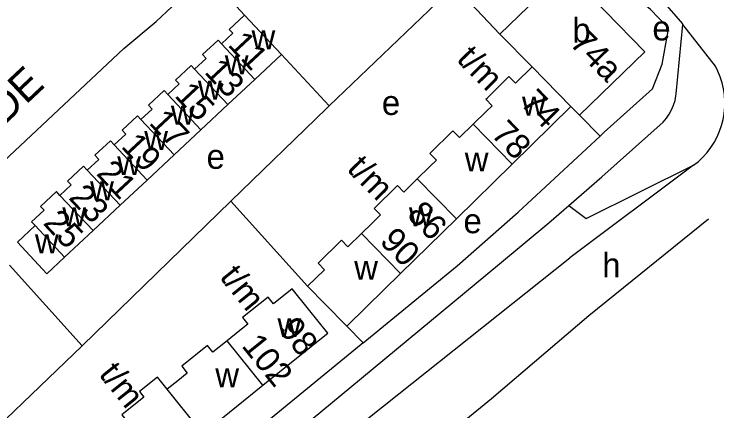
# Model space of a CAD drawing. Extents: x 161141 to 163125, y 381621 to 383200.
# Drawn here: x 162382.8 to 162497.1, y 381773.2 to 381837.8 of the extents above; entities that cross this region are included whole.
import ezdxf

# ---------------------------------------------------------------- set-up
doc = ezdxf.new("R2010")
doc.units = 0
for name, color, linetype in [('BLT_Basislijn', 7, 'Continuous'), ('BLT_Bebouwing', 7, 'Continuous'), ('BLT_Centroide', 7, 'Continuous'), ('BLT_Huisnummer', 7, 'Continuous'), ('BLT_Huisnummer_ tussenligend', 7, 'Continuous'), ('BLT_Huisnummer_reeks', 7, 'Continuous'), ('BLT_Onderverdeling_panden', 7, 'Continuous'), ('BLT_Straatnaam', 7, 'Continuous'), ('BLT_Vlakafsluiter', 7, 'Continuous')]:
    doc.layers.add(name, color=color, linetype=linetype)

msp = doc.modelspace()

# ---------------------------------------------------------------- linework, layer by layer
at = {"layer": 'BLT_Basislijn'}
for p, q in [((162414.1, 381844.29), (162420.31, 381837.61)), ((162461.81, 381834.53), (162454.36, 381842.38)), ((162490.46, 381824.8), (162491.54, 381836.11)), ((162491.54, 381836.11), (162491.45, 381836.22)), ((162496.85, 381829.3), (162491.54, 381836.11)), ((162434.07, 381822.85), (162426.31, 381831.19)), ((162478.08, 381817.94), (162474.76, 381821.34)), ((162464.78, 381805.57), (162478.08, 381817.94)), ((162393.89, 381783.83), (162418.1, 381807.37)), ((162430.56, 381793.5), (162418.1, 381807.37)), ((162476.27, 381788.75), (162495.69, 381804.49)), ((162382.12, 381796.96), (162393.89, 381783.83)), ((162439.57, 381784.3), (162436.92, 381787.02)), ((162367.84, 381758.79), (162393.89, 381783.83)), ((162416.56, 381759.84), (162439.32, 381778.56))]:
    msp.add_line(p, q, dxfattribs=at)
for points in [[(162451.86, 381872.61), (162467.34, 381859.82), (162479.4, 381849.56), (162484.61, 381844.16), (162491.45, 381836.22)], [(162488.94, 381835.49), (162488.88, 381835.83), (162486.28, 381838.55), (162476.14, 381846.96), (162472.45, 381850.34), (162467.02, 381854.86)], [(162373.17, 381806.36), (162400.66, 381832.19), (162405.95, 381836.6), (162413.57, 381843.79), (162414.1, 381844.29)], [(162434.07, 381822.85), (162453.97, 381842), (162454.36, 381842.38)], [(162488.15, 381829.64), (162489.07, 381834.73), (162488.94, 381835.49)], [(162478.08, 381817.94), (162478.77, 381818.58), (162486.59, 381825.6), (162488.15, 381829.64)], [(162498.1, 381820.61), (162498.25, 381821.63), (162498.34, 381822.63), (162498.36, 381823.64), (162498.29, 381824.64), (162498.14, 381825.64), (162497.92, 381826.61), (162497.62, 381827.57), (162497.24, 381828.51), (162496.85, 381829.3)], [(162488.35, 381820.21), (162488.87, 381820.83), (162489.32, 381821.49), (162489.71, 381822.2), (162490.02, 381822.94), (162490.26, 381823.72), (162490.42, 381824.51), (162490.46, 381824.8)], [(162434.07, 381822.85), (162433.64, 381822.43), (162418.1, 381807.37)], [(162472.99, 381806.65), (162478.36, 381811.3), (162488.35, 381820.21)], [(162493.29, 381813.19), (162494.07, 381813.82), (162494.8, 381814.52), (162495.47, 381815.27), (162496.08, 381816.07), (162496.62, 381816.91), (162497.1, 381817.8), (162497.5, 381818.72), (162497.83, 381819.67), (162498.1, 381820.61)], [(162472.99, 381806.65), (162475.84, 381804.55), (162493.29, 381813.19)], [(162439.32, 381778.56), (162461.72, 381797.17), (162469.73, 381803.83), (162472.99, 381806.65)], [(162439.57, 381784.3), (162454.87, 381796.81), (162464.78, 381805.57)], [(162428.68, 381762.74), (162473.16, 381798.14)], [(162443.23, 381761.14), (162460.45, 381775.25), (162476.27, 381788.75)], [(162439.57, 381784.3), (162439.24, 381784.03), (162407.7, 381758.1), (162404.51, 381755.23), (162398.2, 381750)]]:
    msp.add_lwpolyline(points, dxfattribs=at)
at = {"layer": 'BLT_Bebouwing'}
for p, q in [((162461.81, 381834.53), (162472.45, 381844.9)), ((162467.02, 381829.21), (162461.81, 381834.53)), ((162426.31, 381831.19), (162421.99, 381827.15)), ((162421.99, 381827.15), (162417.6, 381823.05)), ((162417.6, 381823.05), (162413.22, 381818.95)), ((162463.82, 381813.38), (162473.35, 381822.75)), ((162474.76, 381821.34), (162473.35, 381822.75)), ((162413.22, 381818.95), (162408.86, 381814.88)), ((162408.86, 381814.88), (162404.49, 381810.79)), ((162454.74, 381804.49), (162463.82, 381813.38)), ((162404.49, 381810.79), (162400.09, 381806.68)), ((162400.09, 381806.68), (162395.68, 381802.56)), ((162445.67, 381795.6), (162454.74, 381804.49)), ((162413.51, 381769.56), (162423.3, 381777.43))]:
    msp.add_line(p, q, dxfattribs=at)
for points in [[(162472.45, 381844.9), (162485.33, 381831.63), (162474.76, 381821.34)], [(162420.31, 381837.61), (162417.83, 381835.3), (162418.42, 381834.67), (162416.58, 381832.94)], [(162426.31, 381831.19), (162423.72, 381833.96), (162420.31, 381837.61)], [(162416.58, 381832.94), (162416, 381833.56), (162413.46, 381831.19), (162414.04, 381830.57), (162412.19, 381828.84)], [(162412.19, 381828.84), (162411.63, 381829.43), (162409.08, 381827.05), (162409.67, 381826.42), (162407.83, 381824.71)], [(162457.45, 381819.87), (162459.65, 381822.01), (162460.53, 381822.86), (162459.49, 381823.92), (162459.71, 381824.13), (162463.27, 381827.63), (162464.32, 381826.57), (162467.02, 381829.21)], [(162407.83, 381824.71), (162407.24, 381825.34), (162404.7, 381822.97), (162405.29, 381822.34), (162403.47, 381820.65)], [(162403.47, 381820.65), (162402.91, 381821.25), (162400.4, 381818.9), (162400.99, 381818.26), (162399.13, 381816.53)], [(162448.37, 381810.99), (162450.42, 381812.99), (162451.48, 381814.03), (162450.43, 381815.1), (162454.18, 381818.78), (162455.23, 381817.71), (162457.45, 381819.87)], [(162399.13, 381816.53), (162398.52, 381817.17), (162395.99, 381814.81), (162396.61, 381814.15), (162394.74, 381812.41)], [(162394.74, 381812.41), (162394.12, 381813.06), (162391.52, 381810.63), (162392.12, 381809.99), (162390.31, 381808.3)], [(162439.3, 381802.1), (162441.05, 381803.8), (162442.38, 381805.11), (162441.36, 381806.16), (162445.15, 381809.88), (162446.17, 381808.84), (162448.37, 381810.99)], [(162390.31, 381808.3), (162389.73, 381808.92), (162387.14, 381806.5), (162387.73, 381805.87), (162385.7, 381803.97), (162386.26, 381803.37)], [(162386.26, 381803.37), (162383.39, 381800.69), (162388.19, 381795.56), (162391.06, 381798.24)], [(162391.06, 381798.24), (162395.68, 381802.56)], [(162430.56, 381793.5), (162433.31, 381796.2), (162432.26, 381797.27), (162436.07, 381801.01), (162437.1, 381799.95), (162439.3, 381802.1)], [(162436.92, 381787.02), (162440.16, 381790.2), (162445.67, 381795.6)], [(162423.3, 381777.43), (162431.48, 381784.01), (162433.84, 381785.9), (162430.71, 381789.8), (162428.06, 381793.09), (162425.03, 381790.66), (162424.15, 381791.76), (162419.99, 381788.42), (162420.84, 381787.35), (162419.54, 381786.3), (162417.5, 381784.66)], [(162436.92, 381787.02), (162433.41, 381790.59), (162430.56, 381793.5)], [(162417.5, 381784.66), (162415.17, 381782.78), (162414.3, 381783.86), (162410.11, 381780.49), (162411, 381779.37), (162409.46, 381778.14), (162407.74, 381776.75)], [(162407.74, 381776.75), (162406.86, 381777.85), (162406.15, 381778.73), (162403.22, 381776.37), (162403.93, 381775.49), (162400.36, 381772.62), (162401.23, 381771.53), (162399.79, 381770.37), (162397.88, 381768.85)]]:
    msp.add_lwpolyline(points, dxfattribs=at)
at = {"layer": 'BLT_Onderverdeling_panden'}
for p, q in [((162421.99, 381827.15), (162416.58, 381832.94)), ((162417.6, 381823.05), (162412.19, 381828.84)), ((162473.35, 381822.75), (162467.02, 381829.21)), ((162413.22, 381818.95), (162407.83, 381824.71)), ((162408.86, 381814.88), (162403.47, 381820.65)), ((162457.45, 381819.87), (162463.82, 381813.38)), ((162404.49, 381810.79), (162399.13, 381816.53)), ((162400.09, 381806.68), (162394.74, 381812.41)), ((162448.37, 381810.99), (162454.74, 381804.49)), ((162395.68, 381802.56), (162390.31, 381808.3)), ((162439.3, 381802.1), (162445.67, 381795.6)), ((162423.3, 381777.43), (162417.5, 381784.66)), ((162413.51, 381769.56), (162407.74, 381776.75))]:
    msp.add_line(p, q, dxfattribs=at)
msp.add_lwpolyline([(162386.26, 381803.37), (162391.06, 381798.24)], dxfattribs=at)
at = {"layer": 'BLT_Vlakafsluiter'}
msp.add_line((162493.29, 381813.19), (162473.16, 381798.14), dxfattribs=at)

# ---------------------------------------------------------------- texts
at = {"layer": 'BLT_Centroide'}
for s, p in [('b', (162473.58, 381833.14)), ('e', (162486.58, 381833.5)), ('w', (162421.44, 381832.06)), ('w', (162417.09, 381828)), ('w', (162412.72, 381823.88)), ('e', (162442.62, 381821.37)), ('w', (162465.4, 381821.28)), ('w', (162408.34, 381819.8)), ('w', (162404, 381815.7)), ('e', (162414.13, 381812.61)), ('w', (162399.61, 381811.59)), ('w', (162456.09, 381812.19)), ('w', (162395.2, 381807.48)), ('w', (162390.69, 381803.27)), ('w', (162447.02, 381803.28)), ('e', (162455.88, 381802.14)), ('w', (162386.24, 381798.89)), ('h', (162478.43, 381794.95)), ('w', (162438.12, 381794.56)), ('w', (162425.65, 381785.25)), ('w', (162415.55, 381777.09))]:
    msp.add_text(s, height=4, dxfattribs=at).set_placement(p)
at = {"layer": 'BLT_Huisnummer'}
for s, rotation, p in [('74a', 314.4505, (162472.98, 381832.89)), ('11', 313.0621, (162417.46, 381832.7)), ('15', 313.065, (162408.78, 381824.44)), ('19', 313.0607, (162400.1, 381816.17)), ('23', 313.063, (162391.57, 381807.83))]:
    msp.add_text(s, height=4, rotation=rotation, dxfattribs=at).set_placement(p)
at = {"layer": 'BLT_Huisnummer_ tussenligend'}
for s, rotation, p in [('13', 313.0621, (162413.63, 381828.27)), ('17', 313.065, (162404.63, 381820)), ('21', 313.0607, (162396.08, 381811.75)), ('25', 313.063, (162387.43, 381803.69))]:
    msp.add_text(s, height=4, rotation=rotation, dxfattribs=at).set_placement(p)
at = {"layer": 'BLT_Huisnummer_reeks'}
for s, rotation, p in [('t/m', 314.4425, (162454.6, 381830.31)), ('74', 314.4505, (162464.96, 381823.15)), ('78', 314.4437, (162460.2, 381818.1)), ('t/m', 314.4425, (162436.78, 381812.47)), ('86', 314.4425, (162446.53, 381804.97)), ('90', 314.4425, (162442.11, 381800.67)), ('t/m', 308.7985, (162416.13, 381794.98)), ('98', 308.7961, (162425.68, 381786.47)), ('102', 308.7985, (162419.7, 381783.79)), ('t/m', 308.7985, (162396.5, 381779.16))]:
    msp.add_text(s, height=4, rotation=rotation, dxfattribs=at).set_placement(p)
at = {"layer": 'BLT_Straatnaam'}
msp.add_text('DOPHEIDE', height=5, rotation=43.3314, dxfattribs=at).set_placement((162362.61, 381802.06))

doc.saveas('drawing.dxf')
